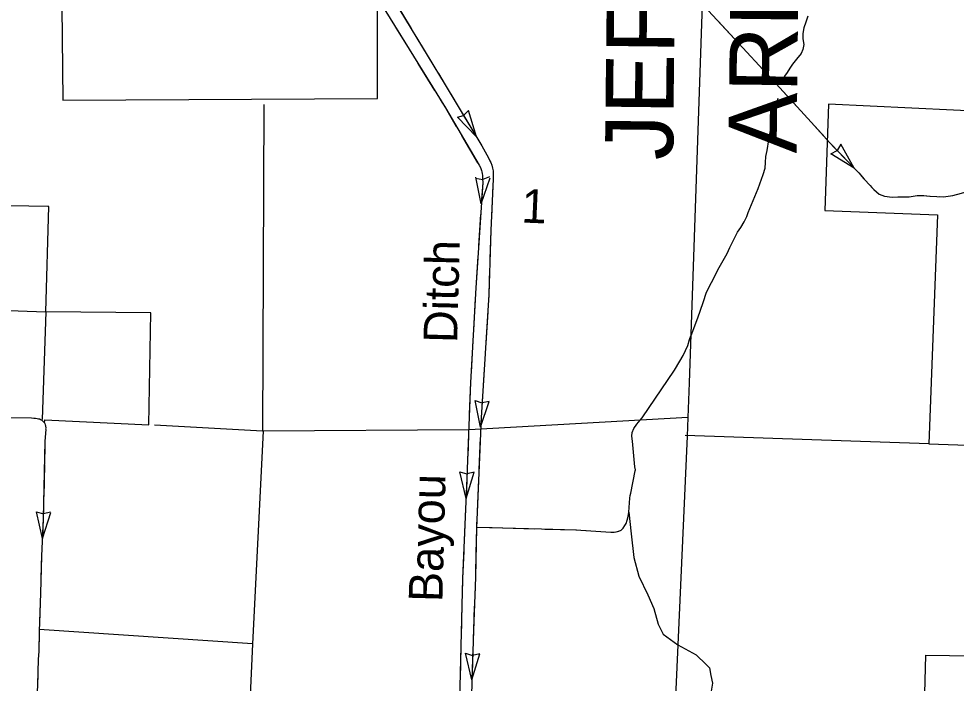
# Model space of a CAD drawing. Extents: x 1196286 to 1268366, y 2040822 to 2082115.
# Drawn here: x 1222892 to 1227299, y 2050559 to 2053681 of the extents above; entities that cross this region are included whole.
import ezdxf

# ---------------------------------------------------------------- set-up
doc = ezdxf.new("R2010")
doc.units = 0
for name, color, linetype in [('55', 7, 'Continuous'), ('60', 7, 'Continuous'), ('62', 7, 'Continuous'), ('63', 7, 'Continuous'), ('Level 70', 7, 'Continuous')]:
    doc.layers.add(name, color=color, linetype=linetype)

msp = doc.modelspace()

# ---------------------------------------------------------------- linework, layer by layer
at = {"layer": '55'}
msp.add_lwpolyline([(1226105.9, 2053795.1), (1226044.2, 2051971.2), (1226037.7, 2051807.6), (1226034.2, 2051719.9), (1225946, 2049758.8), (1225945.2, 2049681.6), (1225876.1, 2047966.3)], dxfattribs=at)
at = {"layer": '60'}
for points in [[(1224043.8, 2053277.6), (1224037.6, 2051743.8)], [(1226037.7, 2051807.6), (1225009.4, 2051749.5)], [(1224037.6, 2051743.8), (1223530.4, 2051770.8)], [(1227171.1, 2051683.7), (1226024.7, 2051722.2)], [(1223991.5, 2050744), (1223948.5, 2049810.4)]]:
    msp.add_lwpolyline(points, dxfattribs=at)
at = {"layer": '62'}
for points in [[(1226601.5, 2053693), (1226591.8, 2053664.5), (1226582.5, 2053638.3), (1226578.4, 2053612.5), (1226578.8, 2053586.5), (1226582.5, 2053560.9), (1226578.1, 2053537.3), (1226569.6, 2053517.8), (1226549, 2053491.4), (1226530.3, 2053467.6), (1226516.6, 2053449.4), (1226503.9, 2053428.8), (1226491.3, 2053411.3), (1226487.8, 2053398.2), (1226484.7, 2053388.9), (1226479.2, 2053374.7)], [(1226043.9, 2052167.5), (1226084.5, 2052275.7), (1226109.9, 2052348.6), (1226125.9, 2052396.9), (1226148.2, 2052441.4), (1226184.7, 2052511.9), (1226222, 2052578.4), (1226235.5, 2052607.1), (1226250.1, 2052637), (1226271.3, 2052678.1), (1226287.3, 2052700.8), (1226302.7, 2052727.3), (1226315, 2052752.7), (1226321.2, 2052771), (1226368.1, 2052883.2), (1226391.4, 2052948.7), (1226400.8, 2052979), (1226403.1, 2053005.3), (1226405, 2053034.2), (1226409.8, 2053061.6), (1226417.6, 2053112.7), (1226430.1, 2053173.8), (1226439.6, 2053214.6), (1226442.2, 2053236.8), (1226445.4, 2053251.4), (1226450.4, 2053266.8), (1226455.5, 2053281.4), (1226457.1, 2053292.2), (1226462.2, 2053308.3)], [(1226911.6, 2052879.6), (1226936.3, 2052856.9), (1226962.1, 2052847.9), (1226998.3, 2052842.5), (1227037.3, 2052844.2), (1227077.4, 2052845.2), (1227116.4, 2052850.3), (1227146.4, 2052851), (1227176.7, 2052847.9), (1227208.5, 2052846.4), (1227240, 2052844.8), (1227283.1, 2052850.2), (1227323.7, 2052861.3)], [(1226911.6, 2052879.6), (1226936.3, 2052856.9), (1226962.1, 2052847.9), (1226975.3, 2052845.9)], [(1226911.6, 2052879.6), (1226936.3, 2052856.9), (1226962.1, 2052847.9), (1226998.3, 2052842.5), (1227037.3, 2052844.2), (1227077.4, 2052845.2), (1227116.4, 2052850.3), (1227146.4, 2052851), (1227176.7, 2052847.9), (1227208.5, 2052846.4), (1227240, 2052844.8), (1227283.1, 2052850.2), (1227323.7, 2052861.3)], [(1227024.5, 2052843.7), (1227037.3, 2052844.2), (1227077.4, 2052845.2), (1227116.4, 2052850.3), (1227146.4, 2052851), (1227172.5, 2052848.3)], [(1227222, 2052845.7), (1227240, 2052844.8), (1227283.1, 2052850.2), (1227323.7, 2052861.3), (1227366.6, 2052874.7)], [(1225760.7, 2051363), (1225765.6, 2051429.2), (1225767.1, 2051441.6), (1225769.1, 2051451.4), (1225790.7, 2051556.4), (1225791, 2051562.1), (1225789, 2051575.2), (1225777, 2051696.7), (1225774.9, 2051720.1), (1225776.2, 2051737.2), (1225783.7, 2051756.6), (1225798.6, 2051776.2), (1225812.9, 2051795.3), (1225823.2, 2051806.3), (1225974.5, 2052029.9), (1226000.7, 2052072.4), (1226016.4, 2052099.2), (1226027.2, 2052121.6), (1226037.1, 2052146.1), (1226045.5, 2052173.8), (1226051.6, 2052191)], [(1225760.7, 2051363), (1225771.1, 2051261.6), (1225784.5, 2051150), (1225806.9, 2051062.3), (1225849.6, 2050973.6), (1225877.1, 2050909.9), (1225898.2, 2050836.3), (1225922.4, 2050788.8), (1225990.1, 2050739.3)], [(1225990.1, 2050739.3), (1226076, 2050692.8), (1226123.1, 2050646.2), (1226140.1, 2050630.8), (1226145.9, 2050595.8), (1226152.8, 2050559.2), (1226144.9, 2050503.4)]]:
    msp.add_lwpolyline(points, dxfattribs=at)
at = {"layer": '63'}
for p, q in [((1225007.1, 2053249.9), (1224982.6, 2053226.2)), ((1225043.7, 2053126.5), (1225007.1, 2053249.9)), ((1224954.3, 2053219.1), (1224982.6, 2053226.2)), ((1225043.7, 2053126.5), (1224954.3, 2053219.1)), ((1226757.3, 2053092.2), (1226739.7, 2053062.8)), ((1226819.9, 2052979.7), (1226757.3, 2053092.2)), ((1226709.4, 2053045.8), (1226739.4, 2053062.5)), ((1226819.9, 2052979.7), (1226709.4, 2053045.8)), ((1225066.6, 2052811.3), (1225041.5, 2052937.5)), ((1225105.9, 2052938.1), (1225073.6, 2052926.6)), ((1225039.5, 2052932.6), (1225073.2, 2052926.5)), ((1225066.6, 2052811.3), (1225108, 2052933.2)), ((1225062.8, 2051761.4), (1225037.3, 2051887.6)), ((1225037.3, 2051887.6), (1225069.8, 2051876.6)), ((1225062.8, 2051761.4), (1225103.8, 2051883.4)), ((1225103.8, 2051883.4), (1225070.2, 2051876.6)), ((1224994.9, 2051427.3), (1224966.3, 2051552.7)), ((1224966.3, 2051552.7), (1224999.1, 2051542.6)), ((1224994.9, 2051427.3), (1225032.9, 2051550.2)), ((1225032.9, 2051550.2), (1224999.5, 2051542.6)), ((1222975.1, 2051364.1), (1223008, 2051354.5)), ((1223003.4, 2051239.1), (1222975.9, 2051364.9)), ((1223003.4, 2051239.1), (1223042.4, 2051361.8)), ((1223041.7, 2051362.6), (1223008.5, 2051354.5)), ((1225022.3, 2050574.1), (1224992.8, 2050699.4)), ((1224992.8, 2050699.4), (1225025.6, 2050689.5)), ((1225022.3, 2050574.1), (1225059.4, 2050697.4)), ((1225059.4, 2050697.4), (1225026.1, 2050689.5))]:
    msp.add_line(p, q, dxfattribs=at)
for points in [[(1224597.4, 2053748), (1224897.7, 2053262.7), (1225056.1, 2052993.1), (1225062.5, 2052981.7), (1225067.3, 2052968.2), (1225070, 2052955.6), (1225072, 2052943.5), (1225073.1, 2052929.7), (1225073.3, 2052912.5), (1225040.9, 2052416.6)], [(1224657.6, 2053766.1), (1224897.6, 2053370.3), (1225068.6, 2053084.8), (1225100.8, 2053027), (1225107.5, 2053013.8), (1225111.1, 2053005.3), (1225116.3, 2052992.5), (1225120, 2052979.2), (1225121.7, 2052966.3), (1225122.7, 2052950.6), (1225122.9, 2052928.8), (1225110.8, 2052686.1), (1225101.8, 2052385.8), (1225065.5, 2051805.5), (1225043.4, 2051288.8), (1225039.1, 2051056.5), (1225029.5, 2050806.5), (1225009.5, 2050156.7)], [(1224660, 2053762.2), (1224737, 2053635.2)], [(1226097.5, 2053761.1), (1226132.9, 2053719.8), (1226257.7, 2053586.1), (1226372.5, 2053460.8), (1226470.4, 2053356.7), (1226617.6, 2053194.5), (1226705.5, 2053097.8), (1226799.7, 2053000.6), (1226841.1, 2052956.7), (1226866.5, 2052928.2), (1226894.2, 2052897), (1226911.6, 2052879.6)], [(1226097.5, 2053761.1), (1226132.9, 2053719.8), (1226257.7, 2053586.1), (1226372.5, 2053460.8), (1226470.4, 2053356.7), (1226617.6, 2053194.5), (1226705.5, 2053097.8), (1226799.7, 2053000.6), (1226841.1, 2052956.7), (1226866.5, 2052928.2), (1226894.2, 2052897), (1226911.6, 2052879.6)], [(1226180.2, 2053669.1), (1226257.7, 2053586.1), (1226281.3, 2053560.3)], [(1224664.7, 2053639.3), (1224742.9, 2053513)], [(1224762.6, 2053592.9), (1224839.6, 2053465.9)], [(1226314.7, 2053523.8), (1226372.5, 2053460.8), (1226415.7, 2053414.9)], [(1224768.9, 2053470.9), (1224847, 2053344.6)], [(1224865.3, 2053423.6), (1224897.6, 2053370.3), (1224941.9, 2053296.3)], [(1226449.6, 2053378.8), (1226470.4, 2053356.7), (1226549.8, 2053269.3)], [(1224873.1, 2053302.5), (1224897.7, 2053262.7), (1224949.2, 2053175)], [(1224967.3, 2053253.9), (1224967.3, 2053253.9), (1224982.6, 2053226.2), (1225043.7, 2053126.5)], [(1226583.1, 2053232.6), (1226617.6, 2053194.5), (1226682.9, 2053122.7)], [(1224974.3, 2053132.3), (1225049.5, 2053004.3)], [(1225069.1, 2053084), (1225100.8, 2053027), (1225107.5, 2053013.8), (1225111.1, 2053005.3), (1225116.3, 2052992.5), (1225120, 2052979.2), (1225121.7, 2052966.3), (1225122.7, 2052950.6), (1225122.7, 2052947.8)], [(1226716.5, 2053086.4), (1226799.7, 2053000.6), (1226819.6, 2052979.5)], [(1225069.2, 2052959.3), (1225070, 2052955.6), (1225072, 2052943.5), (1225073.1, 2052929.7), (1225073.3, 2052912.5), (1225066.6, 2052811.3)], [(1226853.2, 2052943.1), (1226866.5, 2052928.2), (1226894.2, 2052897), (1226903, 2052888.1)], [(1225121.3, 2052898.3), (1225117.7, 2052824.1)], [(1226903, 2052888.1), (1226911.6, 2052879.6)], [(1225117.7, 2052824.1), (1225114, 2052750)], [(1225063.4, 2052761.9), (1225058.6, 2052687.8)], [(1225058.6, 2052687.8), (1225053.7, 2052613.7)], [(1225111.5, 2052700.5), (1225110.8, 2052686.1), (1225106.8, 2052552.1)], [(1225050.5, 2052564.3), (1225040.9, 2052416.6), (1225040.8, 2052416.1)], [(1225105.3, 2052502.6), (1225101.8, 2052385.8), (1225099.9, 2052354.2)], [(1225040.9, 2052416.6), (1225015.8, 2051971.9), (1224997.5, 2051484.9), (1224978.1, 2051051.1)], [(1225038.1, 2052366.7), (1225029.7, 2052218.5)], [(1225096.8, 2052304.8), (1225087.5, 2052156.6)], [(1225026.9, 2052169), (1225018.6, 2052020.8)], [(1225084.4, 2052107.2), (1225075.1, 2051959)], [(1225015.8, 2051971.4), (1225010.2, 2051823)], [(1225072.1, 2051909.6), (1225065.5, 2051805.5), (1225063.6, 2051761.4)], [(1222821.9, 2051807.9), (1222853.2, 2051807), (1222951.7, 2051805.5), (1222962.4, 2051804.9), (1222970.1, 2051804.3), (1222970.4, 2051804.3)], [(1222853.2, 2051807), (1222951.7, 2051805.5), (1222962.4, 2051804.9), (1222970.1, 2051804.3), (1222978.1, 2051803.3), (1222985.2, 2051801.8), (1222989.4, 2051800.7), (1222992.6, 2051799.3), (1222997, 2051796.8), (1223000.9, 2051794.4), (1223004.5, 2051791.2), (1223007.6, 2051788.3), (1223010.5, 2051785), (1223012.8, 2051781.8), (1223014.7, 2051778.7), (1223016.5, 2051773.7), (1223017.7, 2051770.4), (1223018.5, 2051766.6), (1223018.9, 2051759.3), (1223018.7, 2051754.8), (1223018.8, 2051750.5), (1223015.5, 2051695.6), (1223007.8, 2051332.9), (1222999.6, 2051155.7), (1222994.3, 2050982.4), (1222988.1, 2050802.4), (1222986.9, 2050709.5), (1222983.9, 2050670.3), (1222979.9, 2050553.7)], [(1223012.6, 2051782.1), (1223012.8, 2051781.8), (1223014.7, 2051778.7), (1223016.5, 2051773.7), (1223017.7, 2051770.4), (1223018.5, 2051766.6), (1223018.9, 2051759.3), (1223018.7, 2051754.8), (1223018.8, 2051750.5), (1223015.5, 2051695.6), (1223014.2, 2051635)], [(1225008.4, 2051773.5), (1225002.8, 2051625.1)], [(1225061.5, 2051711.9), (1225058.4, 2051637.7)], [(1225058.4, 2051637.7), (1225055.2, 2051563.5)], [(1223013.1, 2051585.5), (1223010, 2051437)], [(1225000.9, 2051575.6), (1224998.2, 2051501.4)], [(1224998.2, 2051501.4), (1224997.5, 2051484.9), (1224994.9, 2051427.3)], [(1225053.1, 2051514.1), (1225046.7, 2051365.7)], [(1223008.9, 2051387.5), (1223007.8, 2051332.9), (1223003.4, 2051239.1)], [(1224992.7, 2051377.8), (1224986.1, 2051229.5)], [(1225043.5, 2051291.9), (1225350.4, 2051284), (1225510.6, 2051279.2), (1225582, 2051275.1), (1225676.2, 2051269), (1225690.8, 2051269.4), (1225700.7, 2051270.5), (1225713.8, 2051273.6), (1225724.4, 2051278.9), (1225733.1, 2051287.8), (1225741.3, 2051299.4), (1225747, 2051310.1), (1225752.8, 2051324.9), (1225757.2, 2051342.4), (1225760.7, 2051363)], [(1225745.1, 2051306.5), (1225747, 2051310.1), (1225752.8, 2051324.9), (1225757.2, 2051342.4), (1225760.7, 2051363)], [(1225044.6, 2051316.3), (1225043.4, 2051288.8), (1225041.1, 2051167.8)], [(1225043.5, 2051291.9), (1225117.8, 2051290)], [(1225167.3, 2051288.7), (1225315.7, 2051284.9)], [(1225365.2, 2051283.5), (1225510.6, 2051279.2), (1225513.6, 2051279)], [(1225563, 2051276.2), (1225582, 2051275.1), (1225676.2, 2051269), (1225690.8, 2051269.4), (1225700.7, 2051270.5), (1225711, 2051272.9)], [(1223001.1, 2051189.7), (1222999.6, 2051155.7), (1222998.3, 2051115.5)], [(1224983.9, 2051180), (1224978.1, 2051051.1)], [(1222998.3, 2051115.5), (1222996.1, 2051041.3)], [(1225040.2, 2051118.3), (1225039.1, 2051056.5), (1225035.7, 2050969.9)], [(1224978.1, 2051051.1), (1224951.7, 2049970.3), (1224960.1, 2049929.6), (1224980.1, 2049878.3), (1225051, 2049744.6), (1225448.7, 2048851.4), (1225789, 2048095.3), (1225855.5, 2047966.3)], [(1224978.1, 2051051.1), (1224976.3, 2050976.9)], [(1222994.6, 2050991.8), (1222994.3, 2050982.4), (1222989.5, 2050843.4)], [(1224975.1, 2050927.4), (1224971.5, 2050778.9)], [(1225033.8, 2050920.4), (1225029.5, 2050806.5), (1225028.4, 2050772)], [(1222988, 2050793.9), (1222986.9, 2050709.5), (1222983.9, 2050670.3), (1222983, 2050645.6)], [(1224970.3, 2050729.4), (1224966.6, 2050581)], [(1225026.9, 2050722.6), (1225022.3, 2050574.1)], [(1222981.4, 2050596.1), (1222979.9, 2050553.7), (1222976.3, 2050447.7)]]:
    msp.add_lwpolyline(points, dxfattribs=at)
at = {"layer": 'Level 70'}
msp.add_line((1223034.2, 2052799.6), (1223028.6, 2052798.4), dxfattribs=at)
for points in [[(1226094.2, 2053796.5), (1226698.2, 2053767.9), (1226712.9, 2054283.4), (1227164.8, 2054265.4), (1227183.9, 2053744.9), (1227682.7, 2053721.4), (1227678.6, 2053233.6), (1226699, 2053279.1), (1226681, 2052780.7), (1227211.5, 2052760.2), (1227171.1, 2051683.7), (1227669.4, 2051667), (1227657.4, 2051038.4)], [(1223028.6, 2052798.4), (1222049.8, 2052816.8), (1222078.1, 2053907)], [(1223093.2, 2053885.6), (1223098.8, 2053298.7), (1224579.5, 2053306.8), (1224578.6, 2053778.4)], [(1223014, 2051782.5), (1223014.3, 2051797.2), (1223504.5, 2051772.3), (1223512.7, 2052298.9), (1223020.3, 2052304.4), (1223034.2, 2052799.6)], [(1222520.4, 2051816), (1222538.5, 2052321.6), (1223020.3, 2052304.4), (1223002.2, 2051797.8)], [(1225007.5, 2051749.7), (1224041.5, 2051743.4), (1223991.5, 2050744)], [(1231056.2, 2048057.5), (1230559.8, 2048076.9), (1229033.8, 2048122.5), (1229048.7, 2048648.2), (1228562.2, 2048668.5), (1228540.1, 2048166.7), (1227567.9, 2048203.2), (1227620.1, 2049667.6), (1227129.1, 2049672.5), (1227157.2, 2050690.5), (1227491.2, 2050685.6), (1227647.6, 2050670.1), (1227657.4, 2051038.4)], [(1223991.5, 2050744), (1222988.2, 2050812.1)]]:
    msp.add_lwpolyline(points, dxfattribs=at)

# ---------------------------------------------------------------- texts
at = {"layer": '60'}
for s, height, rotation, p in [('JEFFERSON CO.', 320, 89.3491, (1225967.7, 2053015.5)), ('ARKANSAS CO.', 320, 89.3491, (1226548.4, 2053048.3)), ('1', 158.4, 357.548, (1225253.2, 2052724.1))]:
    msp.add_text(s, height=height, rotation=rotation, dxfattribs=at).set_placement(p)
at = {"layer": '63'}
for s, p in [('Ditch', (1224953.1, 2052156.5)), ('Bayou', (1224883.6, 2050939.2))]:
    msp.add_text(s, height=158.4, rotation=88.5497, dxfattribs=at).set_placement(p)

doc.saveas('drawing.dxf')
